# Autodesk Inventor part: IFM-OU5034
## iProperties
Created: 2005-12
Part Number: IFM-OU5034
Cost Center: 0,005 kg
Document SubType Name: Modeling
Designer: rsc
Description: Reflexlichttaster
Vendor: IFM
TotalMass: 0,005 kg
Author: rsc
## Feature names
1. Extrusion1
2. Bohrung1 [Hole]
3. Extrusion2
4. Fase1 [Chamfer]
5. Extrusion3
